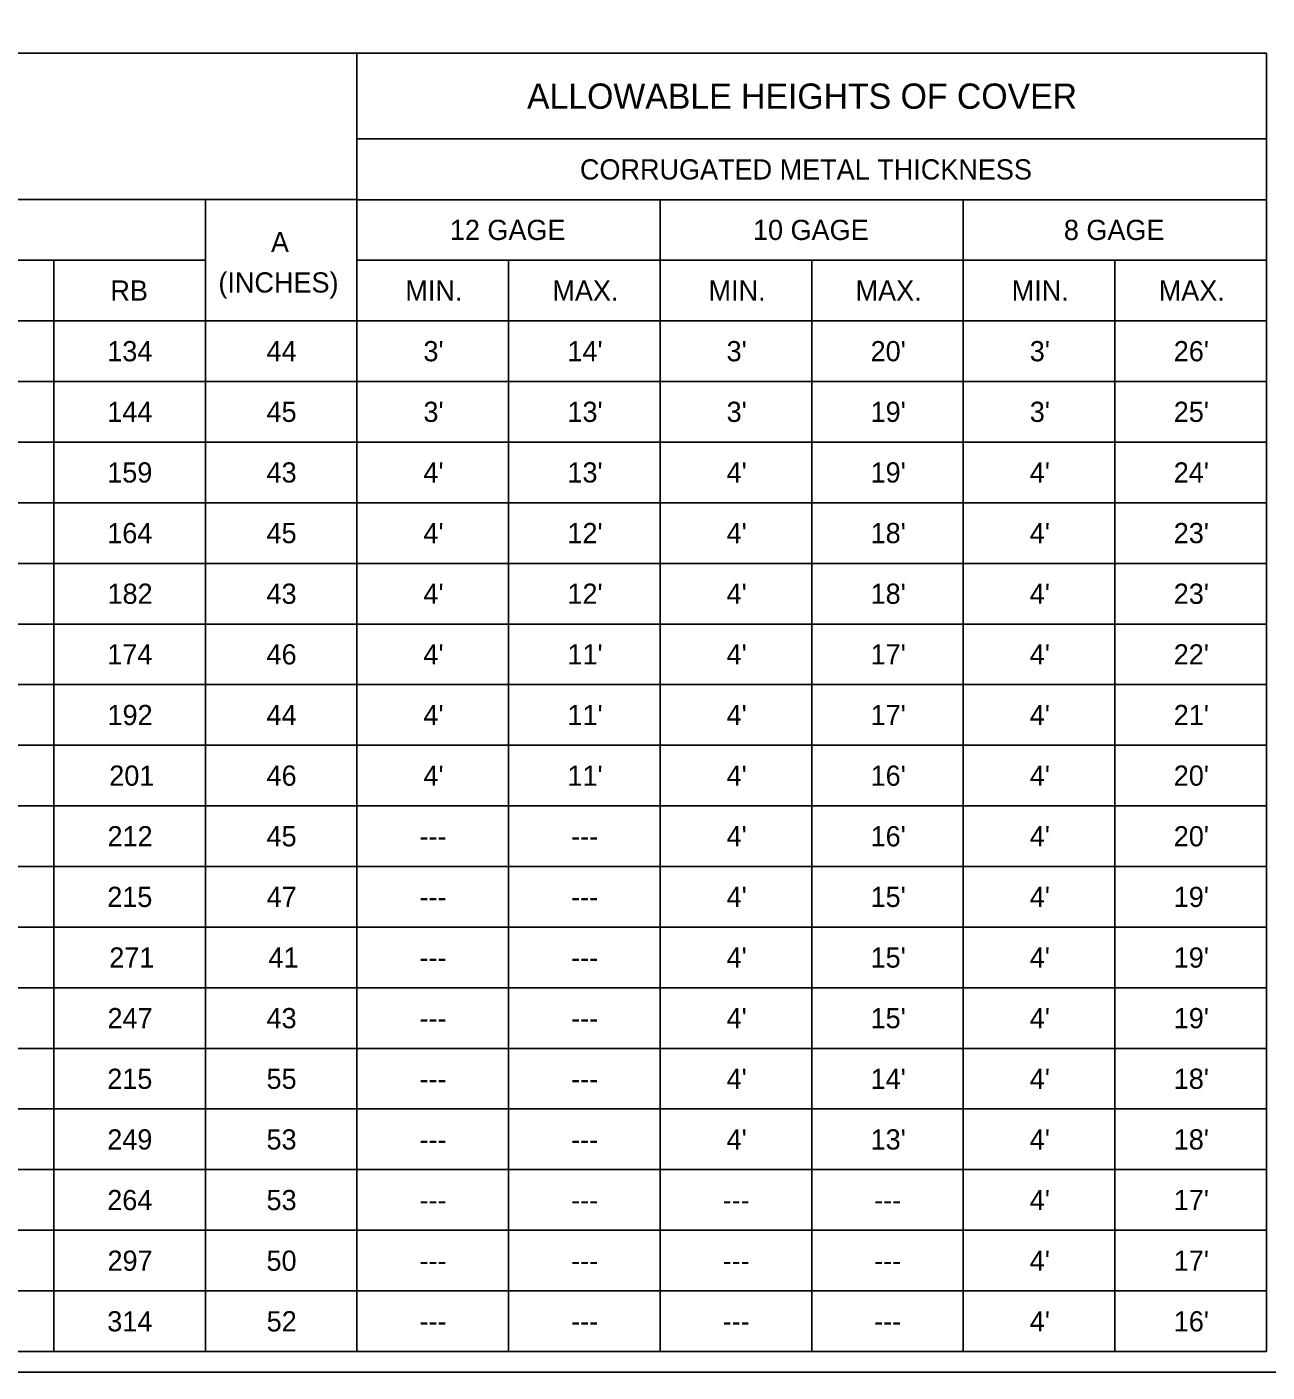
# Model space of a CAD drawing. Extents: x 99862 to 103151, y 100000 to 102076.
# Drawn here: x 101066 to 102048, y 100000 to 101064 of the extents above; entities that cross this region are included whole.
import ezdxf

# ---------------------------------------------------------------- set-up
doc = ezdxf.new("R2010")
doc.units = 0
for name, color, linetype in [('Level 1', 7, 'Continuous'), ('Level 20', 7, 'Continuous'), ('Level 40', 7, 'Continuous')]:
    doc.layers.add(name, color=color, linetype=linetype)

msp = doc.modelspace()

# ---------------------------------------------------------------- linework, layer by layer
at = {"layer": 'Level 1'}
msp.add_lwpolyline([(99862, 99999.5), (103151, 99999.5), (103151, 102075.5), (99862, 102075.5)], close=True, dxfattribs=at)
at = {"layer": 'Level 40'}
for p, q in [((101327.7, 100879.7), (101327.7, 101043.6)), ((101327.7, 100975.7), (102047.7, 100975.7)), ((101327.7, 100831.7), (101327.7, 100975.6)), ((100007.7, 100927.7), (101327.7, 100927.7)), ((101207.7, 100015.8), (101207.7, 100927.7)), ((101327.7, 100927.6), (102047.7, 100927.6)), ((101567.7, 100015.8), (101567.7, 100927.7)), ((101807.7, 100015.8), (101807.7, 100927.7)), ((100247.7, 100879.7), (101207.7, 100879.7)), ((101087.7, 100015.8), (101087.7, 100879.7)), ((101327.7, 100879.7), (102047.7, 100879.7)), ((101447.7, 100015.8), (101447.7, 100879.7)), ((101687.7, 100015.8), (101687.7, 100879.7)), ((101927.7, 100015.8), (101927.7, 100879.7)), ((100007.7, 100831.7), (102047.7, 100831.7)), ((101327.7, 100015.8), (101327.7, 100831.7)), ((100007.7, 100783.7), (102047.7, 100783.7)), ((100007.7, 100735.7), (102047.7, 100735.7)), ((100007.7, 100687.7), (102047.7, 100687.7)), ((100007.7, 100639.7), (102047.7, 100639.7)), ((100007.7, 100591.7), (102047.7, 100591.7)), ((100007.7, 100543.7), (102047.7, 100543.7)), ((100007.7, 100495.7), (102047.7, 100495.7)), ((100007.7, 100447.7), (102047.7, 100447.7)), ((100007.7, 100399.7), (102047.7, 100399.7)), ((100007.7, 100351.8), (102047.7, 100351.8)), ((100007.7, 100303.8), (102047.7, 100303.8)), ((100007.7, 100255.8), (102047.7, 100255.8)), ((100007.7, 100207.8), (102047.7, 100207.8)), ((100007.7, 100159.8), (102047.7, 100159.8)), ((100007.7, 100111.8), (102047.7, 100111.8)), ((100007.7, 100063.8), (102047.7, 100063.8))]:
    msp.add_line(p, q, dxfattribs=at)
msp.add_lwpolyline([(100007.7, 101043.6), (102047.7, 101043.6), (102047.7, 100015.8), (100007.7, 100015.8)], close=True, dxfattribs=at)

# ---------------------------------------------------------------- texts
at = {"layer": 'Level 20'}
for s, height, p in [('ALLOWABLE HEIGHTS OF COVER', 20, (101462.3, 100999.6)), ('CORRUGATED METAL THICKNESS', 16, (101504.2, 100943.6)), ('12 GAGE', 16, (101401.2, 100895.7)), ('10 GAGE', 16, (101641.2, 100895.7)), ('8 GAGE', 16, (101887.3, 100895.7)), ('A', 16, (101259.6, 100886.1)), ('(INCHES)', 16, (101218, 100854.1)), ('RB', 16, (101132.5, 100847.7)), ('MIN.', 16, (101366, 100847.7)), ('MAX.', 16, (101482.4, 100847.7)), ('MIN.', 16, (101606, 100847.7)), ('MAX.', 16, (101722.4, 100847.7)), ('MIN.', 16, (101846, 100847.7)), ('MAX.', 16, (101962.4, 100847.7)), ('134', 16, (101130, 100799.7)), ('44', 16, (101256.1, 100799.7)), ("3'", 16, (101380.3, 100799.7)), ("14'", 16, (101494.3, 100799.7)), ("3'", 16, (101620.3, 100799.7)), ("20'", 16, (101734.3, 100799.7)), ("3'", 16, (101860.3, 100799.7)), ("26'", 16, (101974.3, 100799.7)), ('144', 16, (101130, 100751.7)), ('45', 16, (101256.1, 100751.7)), ("3'", 16, (101380.3, 100751.7)), ("13'", 16, (101494.3, 100751.7)), ("3'", 16, (101620.3, 100751.7)), ("19'", 16, (101734.3, 100751.7)), ("3'", 16, (101860.3, 100751.7)), ("25'", 16, (101974.3, 100751.7)), ('159', 16, (101130, 100703.7)), ('43', 16, (101256.1, 100703.7)), ("4'", 16, (101380.3, 100703.7)), ("13'", 16, (101494.3, 100703.7)), ("4'", 16, (101620.3, 100703.7)), ("19'", 16, (101734.3, 100703.7)), ("4'", 16, (101860.3, 100703.7)), ("24'", 16, (101974.3, 100703.7)), ('164', 16, (101130, 100655.7)), ('45', 16, (101256.1, 100655.7)), ("4'", 16, (101380.3, 100655.7)), ("12'", 16, (101494.3, 100655.7)), ("4'", 16, (101620.3, 100655.7)), ("18'", 16, (101734.3, 100655.7)), ("4'", 16, (101860.3, 100655.7)), ("23'", 16, (101974.3, 100655.7)), ('182', 16, (101130.2, 100607.7)), ('43', 16, (101256.1, 100607.7)), ("4'", 16, (101380.3, 100607.7)), ("12'", 16, (101494.3, 100607.7)), ("4'", 16, (101620.3, 100607.7)), ("18'", 16, (101734.3, 100607.7)), ("4'", 16, (101860.3, 100607.7)), ("23'", 16, (101974.3, 100607.7)), ('174', 16, (101130, 100559.7)), ('46', 16, (101256.1, 100559.7)), ("4'", 16, (101380.3, 100559.7)), ("11'", 16, (101494.3, 100559.7)), ("4'", 16, (101620.3, 100559.7)), ("17'", 16, (101734.3, 100559.7)), ("4'", 16, (101860.3, 100559.7)), ("22'", 16, (101974.3, 100559.7)), ('192', 16, (101130.2, 100511.7)), ('44', 16, (101256.1, 100511.7)), ("4'", 16, (101380.3, 100511.7)), ("11'", 16, (101494.3, 100511.7)), ("4'", 16, (101620.3, 100511.7)), ("17'", 16, (101734.3, 100511.7)), ("4'", 16, (101860.3, 100511.7)), ("21'", 16, (101974.3, 100511.7)), ('201', 16, (101131.6, 100463.7)), ('46', 16, (101256.1, 100463.7)), ("4'", 16, (101380.3, 100463.7)), ("11'", 16, (101494.3, 100463.7)), ("4'", 16, (101620.3, 100463.7)), ("16'", 16, (101734.3, 100463.7)), ("4'", 16, (101860.3, 100463.7)), ("20'", 16, (101974.3, 100463.7)), ('212', 16, (101130.2, 100415.7)), ('45', 16, (101256.1, 100415.7)), ("4'", 16, (101620.3, 100415.7)), ("16'", 16, (101734.3, 100415.7)), ("4'", 16, (101860.3, 100415.7)), ("20'", 16, (101974.3, 100415.7)), ('---', 16, (101377.2, 100415.7)), ('---', 16, (101497.2, 100415.7)), ('215', 16, (101130, 100367.7)), ('47', 16, (101256.2, 100367.7)), ("4'", 16, (101620.3, 100367.7)), ("15'", 16, (101734.3, 100367.7)), ("4'", 16, (101860.3, 100367.7)), ("19'", 16, (101974.3, 100367.7)), ('---', 16, (101377.2, 100367.7)), ('---', 16, (101497.2, 100367.7)), ('271', 16, (101131.6, 100319.7)), ('41', 16, (101257.6, 100319.7)), ("4'", 16, (101620.3, 100319.7)), ("15'", 16, (101734.3, 100319.7)), ("4'", 16, (101860.3, 100319.7)), ("19'", 16, (101974.3, 100319.7)), ('---', 16, (101377.2, 100319.7)), ('---', 16, (101497.2, 100319.7)), ('247', 16, (101130.2, 100271.7)), ('43', 16, (101256.1, 100271.7)), ("4'", 16, (101620.3, 100271.7)), ("15'", 16, (101734.3, 100271.7)), ("4'", 16, (101860.3, 100271.7)), ("19'", 16, (101974.3, 100271.7)), ('---', 16, (101377.2, 100271.7)), ('---', 16, (101497.2, 100271.7)), ('215', 16, (101130, 100223.7)), ('55', 16, (101256.1, 100223.7)), ("4'", 16, (101620.3, 100223.7)), ("14'", 16, (101734.3, 100223.7)), ("4'", 16, (101860.3, 100223.7)), ("18'", 16, (101974.3, 100223.7)), ('---', 16, (101377.2, 100223.7)), ('---', 16, (101497.2, 100223.7)), ('249', 16, (101130, 100175.7)), ('53', 16, (101256.1, 100175.7)), ("4'", 16, (101620.3, 100175.7)), ("13'", 16, (101734.3, 100175.7)), ("4'", 16, (101860.3, 100175.7)), ("18'", 16, (101974.3, 100175.7)), ('---', 16, (101377.2, 100175.7)), ('---', 16, (101497.2, 100175.7)), ('264', 16, (101130, 100127.7)), ('53', 16, (101256.1, 100127.7)), ("4'", 16, (101860.3, 100127.7)), ("17'", 16, (101974.3, 100127.7)), ('---', 16, (101377.2, 100127.7)), ('---', 16, (101497.2, 100127.7)), ('---', 16, (101617.2, 100127.7)), ('---', 16, (101737.2, 100127.7)), ('297', 16, (101130.2, 100079.7)), ('50', 16, (101256.1, 100079.7)), ("4'", 16, (101860.3, 100079.7)), ("17'", 16, (101974.3, 100079.7)), ('---', 16, (101377.2, 100079.7)), ('---', 16, (101497.2, 100079.7)), ('---', 16, (101617.2, 100079.7)), ('---', 16, (101737.2, 100079.7)), ('314', 16, (101130, 100031.7)), ('52', 16, (101256.2, 100031.7)), ("16'", 16, (101974.3, 100031.7)), ('---', 16, (101377.2, 100031.7)), ('---', 16, (101497.2, 100031.7)), ('---', 16, (101617.2, 100031.7)), ('---', 16, (101737.2, 100031.7)), ("4'", 16, (101860.3, 100031.7))]:
    msp.add_text(s, height=height, dxfattribs=at).set_placement(p)

doc.saveas('drawing.dxf')
